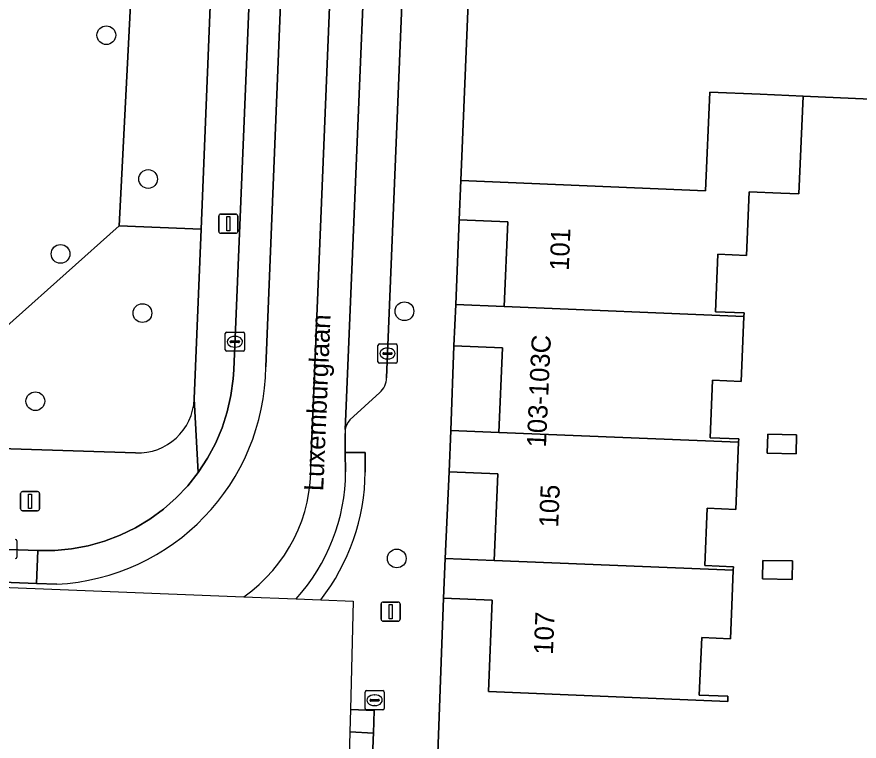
# Model space of a CAD drawing. Extents: x 160786 to 161429, y 386828 to 387485.
# Drawn here: x 161279.33 to 161323.27, y 386888.19 to 386925.96 of the extents above; entities that cross this region are included whole.
import ezdxf

# ---------------------------------------------------------------- set-up
doc = ezdxf.new("R2010")
doc.units = 0
for name, color, linetype in [('IMGEO_Boom', 7, 'Continuous'), ('IMGEO_Erf', 7, 'Continuous'), ('IMGEO_Groenvoorziening', 7, 'Continuous'), ('IMGEO_Hek', 7, 'Continuous'), ('IMGEO_Kolk', 7, 'Continuous'), ('IMGEO_Lichtmast', 7, 'Continuous'), ('IMGEO_Openbare_ruimte_label', 7, 'Continuous'), ('IMGEO_Pand', 7, 'Continuous'), ('IMGEO_Pand_nummerreeks', 7, 'Continuous'), ('IMGEO_Parkeervlak_gesloten', 7, 'Continuous'), ('IMGEO_Rijbaan_lokaal_gesloten', 7, 'Continuous'), ('IMGEO_Rijbaan_lokaal_open', 7, 'Continuous'), ('IMGEO_Voetpad_open', 7, 'Continuous')]:
    doc.layers.add(name, color=color, linetype=linetype)

msp = doc.modelspace()

# ---------------------------------------------------------------- linework, layer by layer
at = {"layer": 'IMGEO_Boom'}
for centre in [(161283.993, 386925.006), (161286.175, 386917.505), (161281.604, 386913.597), (161299.545, 386910.609), (161285.877, 386910.512), (161280.291, 386905.916), (161299.142, 386897.715)]:
    msp.add_circle(centre, 0.489, dxfattribs=at)
at = {"layer": 'IMGEO_Erf'}
msp.add_lwpolyline([(161375.065, 386919.394), (161320.34, 386921.824), (161320.127, 386916.726), (161319.175, 386916.766), (161317.527, 386916.835), (161317.388, 386913.519), (161315.886, 386913.581), (161315.764, 386910.583), (161317.263, 386910.522), (161317.255, 386910.342), (161317.112, 386906.949), (161315.61, 386907.011), (161315.488, 386904.013), (161316.987, 386903.952), (161316.979, 386903.772), (161316.832, 386900.276), (161315.33, 386900.338), (161315.208, 386897.34), (161316.707, 386897.279), (161316.699, 386897.099), (161316.622, 386895.255), (161316.55, 386893.526), (161315.051, 386893.589), (161314.926, 386890.592), (161316.424, 386890.529), (161316.413, 386890.259), (161303.927, 386890.782), (161304.126, 386895.54), (161301.582, 386895.647), (161301.242, 386886.141)], dxfattribs=at)
for points in [[(161302.218, 386910.962), (161304.752, 386910.855), (161304.937, 386915.265), (161302.406, 386915.371)], [(161301.967, 386904.388), (161304.47, 386904.283), (161304.656, 386908.701), (161302.128, 386908.807)], [(161318.473, 386903.212), (161318.504, 386904.204), (161320.005, 386904.158), (161319.975, 386903.166)], [(161301.669, 386897.717), (161304.229, 386897.609), (161304.418, 386902.124), (161301.877, 386902.23)], [(161319.772, 386896.62), (161318.231, 386896.649), (161318.249, 386897.614), (161319.79, 386897.586)]]:
    msp.add_lwpolyline(points, close=True, dxfattribs=at)
at = {"layer": 'IMGEO_Groenvoorziening'}
for points in [[(161288.483, 386952.19), (161278.829, 386952.625), (161256.507, 386953.514), (161239.952, 386954.165), (161238.005, 386908.916), (161247.035, 386908.53), (161246.861, 386904.602), (161249.934, 386904.471), (161250.1, 386908.393), (161276.354, 386907.664), (161284.67, 386915.068), (161285.895, 386939.183)], [(161284.67, 386915.068), (161276.354, 386907.664)], [(161288.941, 386914.885), (161284.67, 386915.068)], [(161288.581, 386906.034), (161288.941, 386914.885)], [(161276.289, 386903.527), (161285.519, 386903.217)]]:
    msp.add_lwpolyline(points, dxfattribs=at)
for points in [[(161288.941, 386914.885), (161289.921, 386939.02), (161285.895, 386939.183), (161284.67, 386915.068)], [(161375.253, 386926.43), (161370.258, 386926.64), (161367.184, 386926.77), (161360.13, 386926.991), (161349.258, 386927.448), (161342.263, 386927.744), (161331.342, 386928.203), (161324.27, 386928.456), (161318.32, 386928.707), (161313.324, 386928.917), (161306.205, 386929.1), (161302.982, 386929.236), (161302.493, 386917.433), (161315.258, 386916.897), (161315.473, 386922.033), (161318.102, 386921.923), (161320.34, 386921.824), (161375.065, 386919.394)]]:
    msp.add_lwpolyline(points, close=True, dxfattribs=at)
msp.add_arc((161285.641, 386906.157), 2.942, 267.6153, 357.612, dxfattribs=at)
at = {"layer": 'IMGEO_Hek'}
for points in [[(161284.67, 386915.068), (161285.895, 386939.183)], [(161276.354, 386907.664), (161284.67, 386915.068)]]:
    msp.add_lwpolyline(points, dxfattribs=at)
at = {"layer": 'IMGEO_Kolk'}
for p, q in [((161290.2, 386908.593), (161290.2, 386909.445)), ((161290.275, 386909.519), (161291.127, 386909.519)), ((161291.201, 386909.445), (161291.201, 386908.593)), ((161290.459, 386909.013), (161290.459, 386909.025)), ((161290.897, 386908.976), (161290.499, 386908.976)), ((161290.502, 386909.062), (161290.9, 386909.062)), ((161290.688, 386909.299), (161290.713, 386909.299)), ((161290.943, 386909.025), (161290.943, 386909.013)), ((161298.238, 386908.904), (161299.09, 386908.904)), ((161291.127, 386908.519), (161290.275, 386908.519)), ((161290.711, 386908.739), (161290.686, 386908.739)), ((161298.163, 386907.978), (161298.163, 386908.83)), ((161298.465, 386908.447), (161298.863, 386908.447)), ((161298.651, 386908.684), (161298.676, 386908.684)), ((161299.164, 386908.83), (161299.164, 386907.978)), ((161298.422, 386908.398), (161298.422, 386908.41)), ((161298.86, 386908.361), (161298.462, 386908.361)), ((161298.674, 386908.124), (161298.649, 386908.124)), ((161298.906, 386908.41), (161298.906, 386908.398)), ((161299.09, 386907.904), (161298.238, 386907.904)), ((161279.325, 386898.635), (161279.325, 386897.783)), ((161297.49, 386889.894), (161297.49, 386890.746)), ((161297.565, 386890.82), (161298.417, 386890.82)), ((161297.978, 386890.6), (161298.003, 386890.6)), ((161298.491, 386890.746), (161298.491, 386889.894)), ((161297.749, 386890.314), (161297.749, 386890.326)), ((161298.187, 386890.277), (161297.789, 386890.277)), ((161297.792, 386890.363), (161298.19, 386890.363)), ((161298.001, 386890.04), (161297.976, 386890.04)), ((161298.233, 386890.326), (161298.233, 386890.314)), ((161298.417, 386889.82), (161297.565, 386889.82))]:
    msp.add_line(p, q, dxfattribs=at)
for points in [[(161290.2, 386908.593), (161290.2, 386909.445)], [(161290.275, 386909.519), (161291.127, 386909.519)], [(161291.201, 386909.445), (161291.201, 386908.593)], [(161298.238, 386908.904), (161299.09, 386908.904)], [(161291.127, 386908.519), (161290.275, 386908.519)], [(161298.163, 386907.978), (161298.163, 386908.83)], [(161299.164, 386908.83), (161299.164, 386907.978)], [(161299.09, 386907.904), (161298.238, 386907.904)], [(161279.325, 386898.635), (161279.325, 386897.783)], [(161297.49, 386889.894), (161297.49, 386890.746)], [(161297.565, 386890.82), (161298.417, 386890.82)], [(161298.491, 386890.746), (161298.491, 386889.894)], [(161298.417, 386889.82), (161297.565, 386889.82)]]:
    msp.add_lwpolyline(points, dxfattribs=at)
for centre, radius, start, end in [((161290.277, 386909.443), 0.0765, 91.552, 178.448), ((161290.277, 386909.443), 0.0765, 91.552, 178.448), ((161291.125, 386909.443), 0.0765, 1.552, 88.448), ((161291.125, 386909.443), 0.0765, 1.552, 88.448), ((161290.499, 386909.022), 0.0403, 85.8775, 175.7526), ((161290.496, 386909.012), 0.0366, 178.938, 274.7102), ((161290.9, 386909.019), 0.043, 264.8664, 352.4533), ((161290.904, 386909.024), 0.0386, 1.7309, 96.639), ((161298.24, 386908.828), 0.0765, 91.552, 178.448), ((161298.24, 386908.828), 0.0765, 91.552, 178.448), ((161299.088, 386908.828), 0.0765, 1.552, 88.448), ((161299.088, 386908.828), 0.0765, 1.552, 88.448), ((161290.277, 386908.595), 0.0765, 181.552, 268.448), ((161290.277, 386908.595), 0.0765, 181.552, 268.448), ((161291.125, 386908.595), 0.0765, 271.552, 358.448), ((161291.125, 386908.595), 0.0765, 271.552, 358.448), ((161298.462, 386908.407), 0.0403, 85.8775, 175.7526), ((161298.867, 386908.409), 0.0386, 1.7309, 96.639), ((161298.459, 386908.397), 0.0366, 178.938, 274.7102), ((161298.863, 386908.404), 0.043, 264.8664, 352.4533), ((161298.24, 386907.98), 0.0765, 181.552, 268.448), ((161298.24, 386907.98), 0.0765, 181.552, 268.448), ((161299.088, 386907.98), 0.0765, 271.552, 358.448), ((161299.088, 386907.98), 0.0765, 271.552, 358.448), ((161279.249, 386898.633), 0.0765, 1.552, 88.448), ((161279.249, 386898.633), 0.0765, 1.552, 88.448), ((161279.249, 386897.785), 0.0765, 271.552, 358.448), ((161279.249, 386897.785), 0.0765, 271.552, 358.448), ((161297.567, 386890.744), 0.0765, 91.552, 178.448), ((161297.567, 386890.744), 0.0765, 91.552, 178.448), ((161298.415, 386890.744), 0.0765, 1.552, 88.448), ((161298.415, 386890.744), 0.0765, 1.552, 88.448), ((161297.789, 386890.323), 0.0403, 85.8775, 175.7526), ((161297.786, 386890.313), 0.0366, 178.938, 274.7102), ((161298.19, 386890.32), 0.043, 264.8664, 352.4533), ((161298.194, 386890.325), 0.0386, 1.7309, 96.639), ((161297.567, 386889.896), 0.0765, 181.552, 268.448), ((161297.567, 386889.896), 0.0765, 181.552, 268.448), ((161298.415, 386889.896), 0.0765, 271.552, 358.448), ((161298.415, 386889.896), 0.0765, 271.552, 358.448)]:
    msp.add_arc(centre, radius, start, end, dxfattribs=at)
for centre, major_axis, ratio, start_param, end_param in [((161290.687, 386909.019), (-0.387, 0.002), 0.722429, 4.712389, 7.853982), ((161290.712, 386909.019), (-0.39, 0.002), 0.717154, 1.570796, 4.712389), ((161298.65, 386908.404), (-0.387, 0.002), 0.722429, 4.712389, 7.853982), ((161298.675, 386908.404), (-0.39, 0.002), 0.717154, 1.570796, 4.712389), ((161297.977, 386890.32), (-0.387, 0.002), 0.722429, 4.712389, 7.853982), ((161298.002, 386890.32), (-0.39, 0.002), 0.717154, 1.570796, 4.712389)]:
    msp.add_ellipse(centre, major_axis=major_axis, ratio=ratio, start_param=start_param, end_param=end_param, dxfattribs=at)
at = {"layer": 'IMGEO_Lichtmast'}
for p, q in [((161289.861, 386914.772), (161289.861, 386915.572)), ((161289.861, 386915.572), (161289.861, 386914.772)), ((161289.961, 386915.672), (161290.751, 386915.672)), ((161290.751, 386915.672), (161289.961, 386915.672)), ((161290.851, 386915.572), (161290.851, 386914.772)), ((161290.851, 386914.772), (161290.851, 386915.572)), ((161290.751, 386914.672), (161289.961, 386914.672)), ((161289.961, 386914.672), (161290.751, 386914.672)), ((161279.519, 386900.3), (161279.519, 386901.1)), ((161279.519, 386901.1), (161279.519, 386900.3)), ((161279.619, 386901.2), (161280.409, 386901.2)), ((161280.409, 386901.2), (161279.619, 386901.2)), ((161280.509, 386901.1), (161280.509, 386900.3)), ((161280.509, 386900.3), (161280.509, 386901.1)), ((161280.409, 386900.2), (161279.619, 386900.2)), ((161279.619, 386900.2), (161280.409, 386900.2)), ((161298.331, 386894.544), (161298.331, 386895.344)), ((161298.331, 386895.344), (161298.331, 386894.544)), ((161298.431, 386895.444), (161299.221, 386895.444)), ((161299.221, 386895.444), (161298.431, 386895.444)), ((161299.321, 386895.344), (161299.321, 386894.544)), ((161299.321, 386894.544), (161299.321, 386895.344)), ((161299.221, 386894.444), (161298.431, 386894.444)), ((161298.431, 386894.444), (161299.221, 386894.444))]:
    msp.add_line(p, q, dxfattribs=at)
for points in [[(161290.281, 386915.547), (161290.431, 386915.547), (161290.431, 386914.797), (161290.281, 386914.797), (161290.281, 386915.547)], [(161279.939, 386901.075), (161280.089, 386901.075), (161280.089, 386900.325), (161279.939, 386900.325), (161279.939, 386901.075)], [(161298.751, 386895.319), (161298.901, 386895.319), (161298.901, 386894.569), (161298.751, 386894.569), (161298.751, 386895.319)]]:
    msp.add_lwpolyline(points, dxfattribs=at)
for centre, start, end in [((161289.961, 386915.572), 90, 180), ((161289.961, 386915.572), 90, 180), ((161290.751, 386915.572), 0, 90), ((161290.751, 386915.572), 360, 90), ((161289.961, 386914.772), 180, 270), ((161289.961, 386914.772), 180, 270), ((161290.751, 386914.772), 270, 0), ((161290.751, 386914.772), 270, 0), ((161279.619, 386901.1), 90, 180), ((161279.619, 386901.1), 90, 180), ((161280.409, 386901.1), 0, 90), ((161280.409, 386901.1), 360, 90), ((161279.619, 386900.3), 180, 270), ((161279.619, 386900.3), 180, 270), ((161280.409, 386900.3), 270, 0), ((161280.409, 386900.3), 270, 0), ((161298.431, 386895.344), 90, 180), ((161298.431, 386895.344), 90, 180), ((161299.221, 386895.344), 0, 90), ((161299.221, 386895.344), 360, 90), ((161298.431, 386894.544), 180, 270), ((161298.431, 386894.544), 180, 270), ((161299.221, 386894.544), 270, 0), ((161299.221, 386894.544), 270, 0)]:
    msp.add_arc(centre, 0.1, start, end, dxfattribs=at)
at = {"layer": 'IMGEO_Pand'}
for points in [[(161317.527, 386916.835), (161319.175, 386916.766), (161320.127, 386916.726), (161320.34, 386921.824), (161318.102, 386921.923), (161315.473, 386922.033), (161315.258, 386916.897), (161302.493, 386917.433), (161302.406, 386915.371), (161304.937, 386915.265), (161304.752, 386910.855), (161317.255, 386910.342), (161317.263, 386910.522), (161315.764, 386910.583), (161315.886, 386913.581), (161317.388, 386913.519)], [(161317.255, 386910.342), (161304.752, 386910.855), (161302.218, 386910.962), (161302.128, 386908.807), (161304.656, 386908.701), (161304.47, 386904.283), (161316.979, 386903.772), (161316.987, 386903.952), (161315.488, 386904.013), (161315.61, 386907.011), (161317.112, 386906.949)], [(161316.979, 386903.772), (161304.47, 386904.283), (161301.967, 386904.388), (161301.877, 386902.23), (161304.418, 386902.124), (161304.229, 386897.609), (161316.699, 386897.099), (161316.707, 386897.279), (161315.208, 386897.34), (161315.33, 386900.338), (161316.832, 386900.276)], [(161318.473, 386903.212), (161319.975, 386903.166), (161320.005, 386904.158), (161318.504, 386904.204)], [(161316.622, 386895.255), (161316.699, 386897.099), (161304.229, 386897.609), (161301.669, 386897.717), (161301.582, 386895.647), (161304.126, 386895.54), (161303.927, 386890.782), (161316.413, 386890.259), (161316.424, 386890.529), (161314.926, 386890.592), (161315.051, 386893.589), (161316.55, 386893.526)], [(161318.231, 386896.649), (161319.772, 386896.62), (161319.79, 386897.586), (161318.249, 386897.614)]]:
    msp.add_lwpolyline(points, close=True, dxfattribs=at)
at = {"layer": 'IMGEO_Parkeervlak_gesloten'}
for points in [[(161298.439, 386951.784), (161298.179, 386945.692), (161296.461, 386904.443)], [(161298.617, 386907.135), (161298.664, 386908.404), (161300.066, 386942.692)], [(161296.689, 386904.945), (161298.255, 386906.372)]]:
    msp.add_lwpolyline(points, dxfattribs=at)
for centre, radius, start, end in [((161297.549, 386907.174), 1.068, 311.3355, 357.9012), ((161297.451, 386904.296), 1, 139.5767, 171.5698)]:
    msp.add_arc(centre, radius, start, end, dxfattribs=at)
at = {"layer": 'IMGEO_Rijbaan_lokaal_gesloten'}
for points in [[(161294.661, 386902.681), (161299.353, 387017.413), (161300.938, 387054.844), (161298.285, 387055.038), (161296.227, 387004.228), (161295.615, 386998.468)], [(161298.691, 386958.606), (161298.922, 386964.506), (161300.177, 386996.031), (161300.266, 386998.149), (161301.03, 387016.276), (161301.348, 387024.011), (161301.576, 387029.9), (161301.584, 387030.091), (161301.604, 387030.255), (161301.823, 387036.16), (161302.586, 387054.794), (161300.938, 387054.844), (161299.353, 387017.413), (161294.661, 386902.681)], [(161292.315, 386907.717), (161295.632, 386989.894), (161295.454, 386994.199)], [(161295.454, 386994.199), (161295.632, 386989.894), (161292.315, 386907.717)], [(161293.806, 386983.797), (161290.641, 386907.552), (161290.611, 386907.092), (161290.494, 386906.22), (161290.3, 386905.361), (161290.03, 386904.523), (161289.686, 386903.713), (161289.271, 386902.937), (161288.788, 386902.201), (161288.242, 386901.511), (161287.636, 386900.872), (161286.975, 386900.29), (161286.265, 386899.77), (161285.512, 386899.315), (161284.72, 386898.929), (161283.898, 386898.615), (161283.051, 386898.376), (161282.185, 386898.214), (161281.309, 386898.13), (161280.429, 386898.124), (161280.349, 386896.413), (161281.403, 386896.371)], [(161296.461, 386904.443), (161298.179, 386945.692), (161298.439, 386951.784)], [(161296.477, 386902.237), (161296.448, 386903.247), (161296.451, 386904.233)], [(161281.403, 386896.371), (161280.349, 386896.413), (161248.174, 386897.682), (161123.39, 386902.685), (161123.374, 386902.409), (161291.165, 386895.721)], [(161291.165, 386895.721), (161293.896, 386895.612)]]:
    msp.add_lwpolyline(points, dxfattribs=at)
msp.add_lwpolyline([(161234.905, 386900.003), (161234.751, 386900.009), (161224.348, 386900.439), (161223.699, 386900.466), (161162.46, 386902.982), (161161.944, 386903.003), (161151.67, 386903.416), (161135.502, 386904.066), (161131.97, 386904.208), (161128.825, 386904.334), (161123.496, 386904.504), (161123.39, 386902.685), (161248.174, 386897.682), (161280.349, 386896.413), (161280.429, 386898.124), (161278.893, 386898.183), (161277.3, 386898.249), (161276.855, 386898.267)], close=True, dxfattribs=at)
for centre, radius, start, end in [((161280.819, 386907.853), 11.497, 272.9115, 359.3226), ((161280.819, 386907.853), 11.497, 272.9115, 359.3226), ((161297.374, 386904.294), 0.925, 170.7474, 183.7999), ((161286.454, 386902.445), 8.211, 305.0109, 1.6445), ((161286.454, 386902.445), 8.211, 305.0109, 1.6445), ((161286.549, 386902.289), 9.928, 317.7351, 359.701)]:
    msp.add_arc(centre, radius, start, end, dxfattribs=at)
at = {"layer": 'IMGEO_Rijbaan_lokaal_open'}
msp.add_lwpolyline([(161295.749, 386851.961), (161295.749, 386851.961), (161296.507, 386851.934), (161296.798, 386859.523), (161296.891, 386861.949), (161297.119, 386867.903), (161297.211, 386870.31), (161297.462, 386876.869), (161297.831, 386885.751), (161297.842, 386886.082), (161297.917, 386888.279), (161297.928, 386888.609), (161296.697, 386888.665)], close=True, dxfattribs=at)
at = {"layer": 'IMGEO_Voetpad_open'}
for points in [[(161293.806, 386983.797), (161291.727, 386983.944), (161291.591, 386981.225), (161290.663, 386957.219), (161290.668, 386957.173), (161290.386, 386950.426), (161289.921, 386939.02), (161288.941, 386914.885), (161288.581, 386906.034), (161288.788, 386902.201), (161289.271, 386902.937), (161289.686, 386903.713), (161290.03, 386904.523), (161290.3, 386905.361), (161290.494, 386906.22), (161290.611, 386907.092), (161290.641, 386907.552)], [(161296.728, 386889.843), (161296.697, 386888.665), (161297.928, 386888.609), (161297.968, 386889.786), (161296.728, 386889.843)]]:
    msp.add_lwpolyline(points, close=True, dxfattribs=at)
for points in [[(161300.345, 386948.662), (161300.203, 386945.628), (161300.066, 386942.692), (161298.664, 386908.404), (161298.617, 386907.135)], [(161301.242, 386886.141), (161301.582, 386895.647), (161301.669, 386897.717), (161301.877, 386902.23), (161301.967, 386904.388), (161302.128, 386908.807), (161302.218, 386910.962), (161302.406, 386915.371), (161302.493, 386917.433), (161302.982, 386929.236)], [(161285.519, 386903.217), (161276.289, 386903.527), (161256.202, 386904.203), (161249.934, 386904.471), (161246.861, 386904.602), (161237.836, 386904.988), (161235.128, 386905.104), (161232.717, 386905.215), (161226.578, 386905.472), (161219.809, 386905.751), (161214.226, 386905.974), (161214.044, 386905.981), (161206.033, 386906.311), (161200.447, 386906.55), (161200.275, 386906.557), (161192.24, 386906.863), (161186.669, 386907.11), (161186.492, 386907.118), (161178.458, 386907.447)], [(161298.255, 386906.372), (161296.689, 386904.945)], [(161276.855, 386898.267), (161277.3, 386898.249), (161278.893, 386898.183), (161280.429, 386898.124), (161281.309, 386898.13), (161282.185, 386898.214), (161283.051, 386898.376), (161283.898, 386898.615), (161284.72, 386898.929), (161285.512, 386899.315), (161286.265, 386899.77), (161286.975, 386900.29), (161287.636, 386900.872), (161288.242, 386901.511), (161288.788, 386902.201), (161288.581, 386906.034)], [(161296.451, 386904.233), (161296.448, 386903.247), (161297.502, 386903.239), (161297.499, 386902.223)], [(161297.499, 386902.223), (161297.502, 386903.239), (161296.448, 386903.247), (161296.477, 386902.237)], [(161293.896, 386895.612), (161295.179, 386895.561)], [(161295.179, 386895.561), (161296.874, 386895.493), (161296.728, 386889.843), (161296.728, 386889.843), (161297.968, 386889.786), (161297.928, 386888.609), (161297.917, 386888.279), (161297.842, 386886.082)]]:
    msp.add_lwpolyline(points, dxfattribs=at)
for centre, radius, start, end in [((161297.549, 386907.174), 1.068, 311.3355, 357.9012), ((161285.641, 386906.157), 2.942, 267.6153, 357.612), ((161297.451, 386904.296), 1, 139.5767, 171.5698), ((161297.374, 386904.294), 0.925, 170.7474, 183.7999), ((161286.549, 386902.289), 9.928, 317.7351, 359.701), ((161286.498, 386902.319), 11.002, 322.1008, 359.5014), ((161286.498, 386902.319), 11.002, 322.1008, 359.5014)]:
    msp.add_arc(centre, radius, start, end, dxfattribs=at)

# ---------------------------------------------------------------- texts
at = {"layer": 'IMGEO_Openbare_ruimte_label'}
msp.add_text('Luxemburglaan', height=1, rotation=87.5926, dxfattribs=at).set_placement((161295.307, 386901.212))
at = {"layer": 'IMGEO_Pand_nummerreeks'}
for s, rotation, p in [('101', 87.6339, (161308.116, 386912.701)), ('103-103C', 87.3933, (161306.925, 386903.487)), ('105', 87.6339, (161307.563, 386899.315)), ('107', 87.6339, (161307.289, 386892.678))]:
    msp.add_text(s, height=1, rotation=rotation, dxfattribs=at).set_placement(p)

doc.saveas('drawing.dxf')
